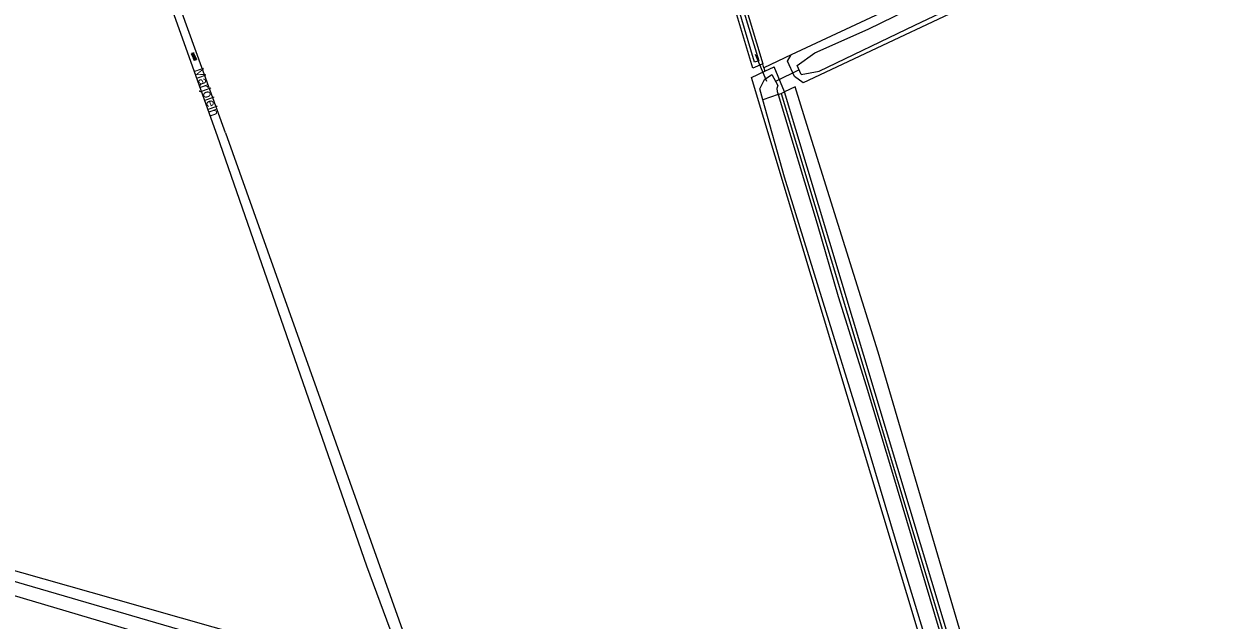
# Model space of a CAD drawing. Extents: x 134297 to 137000, y 403500 to 406000.
# Drawn here: x 135669.7 to 135992.6, y 404160 to 404321.6 of the extents above; entities that cross this region are included whole.
import ezdxf

# ---------------------------------------------------------------- set-up
doc = ezdxf.new("R2010")
doc.units = 0
for name, color, linetype in [('gg-anno-openbare ruimte label', 7, 'Continuous'), ('gg-knt-bronhoudergrens', 7, 'Continuous'), ('gg-knt-onverhard', 7, 'Continuous'), ('gg-kntw-bovenkant insteek waterloop', 7, 'Continuous'), ('gg-kntw-waterlijn', 7, 'Continuous'), ('gg-kwrk-duiker nz buis', 7, 'Continuous'), ('gt-grn-vlakafsluiter', 7, 'Continuous'), ('gt-symb-overige verharding', 7, 'Continuous')]:
    doc.layers.add(name, color=color, linetype=linetype)

# ---------------------------------------------------------------- blocks, each defined once
blk = doc.blocks.new('gt0-OVH')
at = {"layer": 'gt-symb-overige verharding'}
for points in [[(-0.97, 0.3), (-0.97, 0.31), (-0.96, 0.32), (-0.97, 0.33), (-0.97, 0.34), (-0.98, 0.35), (-0.99, 0.35), (-1, 0.36), (-1.01, 0.35), (-1.02, 0.35), (-1.03, 0.34), (-1.03, 0.33), (-1.04, 0.32), (-1.03, 0.31), (-1.03, 0.3), (-1.02, 0.29), (-1.01, 0.29), (-1, 0.28), (-0.99, 0.29), (-0.98, 0.29)], [(-0.87, 0.11), (-0.87, 0.12), (-0.86, 0.13), (-0.87, 0.14), (-0.87, 0.15), (-0.88, 0.16), (-0.89, 0.16), (-0.9, 0.16), (-0.91, 0.16), (-0.92, 0.16), (-0.93, 0.15), (-0.93, 0.14), (-0.94, 0.13), (-0.93, 0.12), (-0.93, 0.11), (-0.92, 0.1), (-0.91, 0.09), (-0.9, 0.09), (-0.89, 0.09), (-0.88, 0.1)], [(-0.77, 0.3), (-0.77, 0.31), (-0.76, 0.32), (-0.77, 0.33), (-0.77, 0.34), (-0.78, 0.35), (-0.79, 0.35), (-0.8, 0.36), (-0.81, 0.35), (-0.82, 0.35), (-0.83, 0.34), (-0.83, 0.33), (-0.84, 0.32), (-0.83, 0.31), (-0.83, 0.3), (-0.82, 0.29), (-0.81, 0.29), (-0.8, 0.28), (-0.79, 0.29), (-0.78, 0.29)], [(-0.67, 0.11), (-0.67, 0.12), (-0.66, 0.13), (-0.67, 0.14), (-0.67, 0.15), (-0.68, 0.16), (-0.69, 0.16), (-0.7, 0.16), (-0.71, 0.16), (-0.72, 0.16), (-0.73, 0.15), (-0.73, 0.14), (-0.74, 0.13), (-0.73, 0.12), (-0.73, 0.11), (-0.72, 0.1), (-0.71, 0.09), (-0.7, 0.09), (-0.69, 0.09), (-0.68, 0.1)], [(-0.57, 0.3), (-0.57, 0.31), (-0.56, 0.32), (-0.57, 0.33), (-0.57, 0.34), (-0.58, 0.35), (-0.59, 0.35), (-0.6, 0.36), (-0.61, 0.35), (-0.62, 0.35), (-0.63, 0.34), (-0.63, 0.33), (-0.64, 0.32), (-0.63, 0.31), (-0.63, 0.3), (-0.62, 0.29), (-0.61, 0.29), (-0.6, 0.28), (-0.59, 0.29), (-0.58, 0.29)], [(-0.47, 0.11), (-0.47, 0.12), (-0.46, 0.13), (-0.47, 0.14), (-0.47, 0.15), (-0.48, 0.16), (-0.49, 0.16), (-0.5, 0.16), (-0.51, 0.16), (-0.52, 0.16), (-0.53, 0.15), (-0.53, 0.14), (-0.54, 0.13), (-0.53, 0.12), (-0.53, 0.11), (-0.52, 0.1), (-0.51, 0.09), (-0.5, 0.09), (-0.49, 0.09), (-0.48, 0.1)], [(-0.37, 0.3), (-0.37, 0.31), (-0.36, 0.32), (-0.37, 0.33), (-0.37, 0.34), (-0.38, 0.35), (-0.39, 0.35), (-0.4, 0.36), (-0.41, 0.35), (-0.42, 0.35), (-0.43, 0.34), (-0.43, 0.33), (-0.44, 0.32), (-0.43, 0.31), (-0.43, 0.3), (-0.42, 0.29), (-0.41, 0.29), (-0.4, 0.28), (-0.39, 0.29), (-0.38, 0.29)], [(-0.27, 0.11), (-0.27, 0.12), (-0.26, 0.13), (-0.27, 0.14), (-0.27, 0.15), (-0.28, 0.16), (-0.29, 0.16), (-0.3, 0.16), (-0.31, 0.16), (-0.32, 0.16), (-0.33, 0.15), (-0.33, 0.14), (-0.34, 0.13), (-0.33, 0.12), (-0.33, 0.11), (-0.32, 0.1), (-0.31, 0.09), (-0.3, 0.09), (-0.29, 0.09), (-0.28, 0.1)], [(-0.17, 0.3), (-0.17, 0.31), (-0.16, 0.32), (-0.17, 0.33), (-0.17, 0.34), (-0.18, 0.35), (-0.19, 0.35), (-0.2, 0.36), (-0.21, 0.35), (-0.22, 0.35), (-0.23, 0.34), (-0.23, 0.33), (-0.24, 0.32), (-0.23, 0.31), (-0.23, 0.3), (-0.22, 0.29), (-0.21, 0.29), (-0.2, 0.28), (-0.19, 0.29), (-0.18, 0.29)], [(-0.07, 0.11), (-0.07, 0.12), (-0.06, 0.13), (-0.07, 0.14), (-0.07, 0.15), (-0.08, 0.16), (-0.09, 0.16), (-0.1, 0.16), (-0.11, 0.16), (-0.12, 0.16), (-0.13, 0.15), (-0.13, 0.14), (-0.14, 0.13), (-0.13, 0.12), (-0.13, 0.11), (-0.12, 0.1), (-0.11, 0.09), (-0.1, 0.09), (-0.09, 0.09), (-0.08, 0.1)], [(0.03, 0.3), (0.03, 0.31), (0.04, 0.32), (0.03, 0.33), (0.03, 0.34), (0.02, 0.35), (0.01, 0.35), (0, 0.36), (-0.01, 0.35), (-0.02, 0.35), (-0.03, 0.34), (-0.03, 0.33), (-0.04, 0.32), (-0.03, 0.31), (-0.03, 0.3), (-0.02, 0.29), (-0.01, 0.29), (0, 0.28), (0.01, 0.29), (0.02, 0.29)], [(0.13, 0.11), (0.13, 0.12), (0.14, 0.13), (0.13, 0.14), (0.13, 0.15), (0.12, 0.16), (0.11, 0.16), (0.1, 0.16), (0.09, 0.16), (0.08, 0.16), (0.07, 0.15), (0.07, 0.14), (0.06, 0.13), (0.07, 0.12), (0.07, 0.11), (0.08, 0.1), (0.09, 0.09), (0.1, 0.09), (0.11, 0.09), (0.12, 0.1)], [(0.23, 0.3), (0.23, 0.31), (0.24, 0.32), (0.23, 0.33), (0.23, 0.34), (0.22, 0.35), (0.21, 0.35), (0.2, 0.36), (0.19, 0.35), (0.18, 0.35), (0.17, 0.34), (0.17, 0.33), (0.16, 0.32), (0.17, 0.31), (0.17, 0.3), (0.18, 0.29), (0.19, 0.29), (0.2, 0.28), (0.21, 0.29), (0.22, 0.29)], [(0.33, 0.11), (0.33, 0.12), (0.34, 0.13), (0.33, 0.14), (0.33, 0.15), (0.32, 0.16), (0.31, 0.16), (0.3, 0.16), (0.29, 0.16), (0.28, 0.16), (0.27, 0.15), (0.27, 0.14), (0.26, 0.13), (0.27, 0.12), (0.27, 0.11), (0.28, 0.1), (0.29, 0.09), (0.3, 0.09), (0.31, 0.09), (0.32, 0.1)], [(0.43, 0.3), (0.43, 0.31), (0.44, 0.32), (0.43, 0.33), (0.43, 0.34), (0.42, 0.35), (0.41, 0.35), (0.4, 0.36), (0.39, 0.35), (0.38, 0.35), (0.37, 0.34), (0.37, 0.33), (0.36, 0.32), (0.37, 0.31), (0.37, 0.3), (0.38, 0.29), (0.39, 0.29), (0.4, 0.28), (0.41, 0.29), (0.42, 0.29)], [(0.53, 0.11), (0.53, 0.12), (0.54, 0.13), (0.53, 0.14), (0.53, 0.15), (0.52, 0.16), (0.51, 0.16), (0.5, 0.16), (0.49, 0.16), (0.48, 0.16), (0.47, 0.15), (0.47, 0.14), (0.46, 0.13), (0.47, 0.12), (0.47, 0.11), (0.48, 0.1), (0.49, 0.09), (0.5, 0.09), (0.51, 0.09), (0.52, 0.1)], [(0.63, 0.3), (0.63, 0.31), (0.64, 0.32), (0.63, 0.33), (0.63, 0.34), (0.62, 0.35), (0.61, 0.35), (0.6, 0.36), (0.59, 0.35), (0.58, 0.35), (0.57, 0.34), (0.57, 0.33), (0.56, 0.32), (0.57, 0.31), (0.57, 0.3), (0.58, 0.29), (0.59, 0.29), (0.6, 0.28), (0.61, 0.29), (0.62, 0.29)], [(0.73, 0.11), (0.73, 0.12), (0.74, 0.13), (0.73, 0.14), (0.73, 0.15), (0.72, 0.16), (0.71, 0.16), (0.7, 0.16), (0.69, 0.16), (0.68, 0.16), (0.67, 0.15), (0.67, 0.14), (0.66, 0.13), (0.67, 0.12), (0.67, 0.11), (0.68, 0.1), (0.69, 0.09), (0.7, 0.09), (0.71, 0.09), (0.72, 0.1)], [(0.83, 0.3), (0.83, 0.31), (0.84, 0.32), (0.83, 0.33), (0.83, 0.34), (0.82, 0.35), (0.81, 0.35), (0.8, 0.36), (0.79, 0.35), (0.78, 0.35), (0.77, 0.34), (0.77, 0.33), (0.76, 0.32), (0.77, 0.31), (0.77, 0.3), (0.78, 0.29), (0.79, 0.29), (0.8, 0.28), (0.81, 0.29), (0.82, 0.29)], [(0.93, 0.11), (0.93, 0.12), (0.94, 0.13), (0.93, 0.14), (0.93, 0.15), (0.92, 0.16), (0.91, 0.16), (0.9, 0.16), (0.89, 0.16), (0.88, 0.16), (0.87, 0.15), (0.87, 0.14), (0.86, 0.13), (0.87, 0.12), (0.87, 0.11), (0.88, 0.1), (0.89, 0.09), (0.9, 0.09), (0.91, 0.09), (0.92, 0.1)], [(1.03, 0.3), (1.03, 0.31), (1.04, 0.32), (1.03, 0.33), (1.03, 0.34), (1.02, 0.35), (1.01, 0.35), (1, 0.36), (0.99, 0.35), (0.98, 0.35), (0.97, 0.34), (0.97, 0.33), (0.96, 0.32), (0.97, 0.31), (0.97, 0.3), (0.98, 0.29), (0.99, 0.29), (1, 0.28), (1.01, 0.29), (1.02, 0.29)], [(-0.97, -0.14), (-0.97, -0.13), (-0.96, -0.12), (-0.97, -0.11), (-0.97, -0.1), (-0.98, -0.09), (-0.99, -0.09), (-1, -0.08), (-1.01, -0.09), (-1.02, -0.09), (-1.03, -0.1), (-1.03, -0.11), (-1.04, -0.12), (-1.03, -0.13), (-1.03, -0.14), (-1.02, -0.15), (-1.01, -0.15), (-1, -0.16), (-0.99, -0.15), (-0.98, -0.15)], [(-0.87, -0.33), (-0.87, -0.32), (-0.86, -0.31), (-0.87, -0.3), (-0.87, -0.29), (-0.88, -0.28), (-0.89, -0.28), (-0.9, -0.28), (-0.91, -0.28), (-0.92, -0.28), (-0.93, -0.29), (-0.93, -0.3), (-0.94, -0.31), (-0.93, -0.32), (-0.93, -0.33), (-0.92, -0.34), (-0.91, -0.35), (-0.9, -0.35), (-0.89, -0.35), (-0.88, -0.34)], [(-0.77, -0.14), (-0.77, -0.13), (-0.76, -0.12), (-0.77, -0.11), (-0.77, -0.1), (-0.78, -0.09), (-0.79, -0.09), (-0.8, -0.08), (-0.81, -0.09), (-0.82, -0.09), (-0.83, -0.1), (-0.83, -0.11), (-0.84, -0.12), (-0.83, -0.13), (-0.83, -0.14), (-0.82, -0.15), (-0.81, -0.15), (-0.8, -0.16), (-0.79, -0.15), (-0.78, -0.15)], [(-0.67, -0.33), (-0.67, -0.32), (-0.66, -0.31), (-0.67, -0.3), (-0.67, -0.29), (-0.68, -0.28), (-0.69, -0.28), (-0.7, -0.28), (-0.71, -0.28), (-0.72, -0.28), (-0.73, -0.29), (-0.73, -0.3), (-0.74, -0.31), (-0.73, -0.32), (-0.73, -0.33), (-0.72, -0.34), (-0.71, -0.35), (-0.7, -0.35), (-0.69, -0.35), (-0.68, -0.34)], [(-0.57, -0.14), (-0.57, -0.13), (-0.56, -0.12), (-0.57, -0.11), (-0.57, -0.1), (-0.58, -0.09), (-0.59, -0.09), (-0.6, -0.08), (-0.61, -0.09), (-0.62, -0.09), (-0.63, -0.1), (-0.63, -0.11), (-0.64, -0.12), (-0.63, -0.13), (-0.63, -0.14), (-0.62, -0.15), (-0.61, -0.15), (-0.6, -0.16), (-0.59, -0.15), (-0.58, -0.15)], [(-0.47, -0.33), (-0.47, -0.32), (-0.46, -0.31), (-0.47, -0.3), (-0.47, -0.29), (-0.48, -0.28), (-0.49, -0.28), (-0.5, -0.28), (-0.51, -0.28), (-0.52, -0.28), (-0.53, -0.29), (-0.53, -0.3), (-0.54, -0.31), (-0.53, -0.32), (-0.53, -0.33), (-0.52, -0.34), (-0.51, -0.35), (-0.5, -0.35), (-0.49, -0.35), (-0.48, -0.34)], [(-0.37, -0.14), (-0.37, -0.13), (-0.36, -0.12), (-0.37, -0.11), (-0.37, -0.1), (-0.38, -0.09), (-0.39, -0.09), (-0.4, -0.08), (-0.41, -0.09), (-0.42, -0.09), (-0.43, -0.1), (-0.43, -0.11), (-0.44, -0.12), (-0.43, -0.13), (-0.43, -0.14), (-0.42, -0.15), (-0.41, -0.15), (-0.4, -0.16), (-0.39, -0.15), (-0.38, -0.15)], [(-0.27, -0.33), (-0.27, -0.32), (-0.26, -0.31), (-0.27, -0.3), (-0.27, -0.29), (-0.28, -0.28), (-0.29, -0.28), (-0.3, -0.28), (-0.31, -0.28), (-0.32, -0.28), (-0.33, -0.29), (-0.33, -0.3), (-0.34, -0.31), (-0.33, -0.32), (-0.33, -0.33), (-0.32, -0.34), (-0.31, -0.35), (-0.3, -0.35), (-0.29, -0.35), (-0.28, -0.34)], [(-0.17, -0.14), (-0.17, -0.13), (-0.16, -0.12), (-0.17, -0.11), (-0.17, -0.1), (-0.18, -0.09), (-0.19, -0.09), (-0.2, -0.08), (-0.21, -0.09), (-0.22, -0.09), (-0.23, -0.1), (-0.23, -0.11), (-0.24, -0.12), (-0.23, -0.13), (-0.23, -0.14), (-0.22, -0.15), (-0.21, -0.15), (-0.2, -0.16), (-0.19, -0.15), (-0.18, -0.15)], [(-0.07, -0.33), (-0.07, -0.32), (-0.06, -0.31), (-0.07, -0.3), (-0.07, -0.29), (-0.08, -0.28), (-0.09, -0.28), (-0.1, -0.28), (-0.11, -0.28), (-0.12, -0.28), (-0.13, -0.29), (-0.13, -0.3), (-0.14, -0.31), (-0.13, -0.32), (-0.13, -0.33), (-0.12, -0.34), (-0.11, -0.35), (-0.1, -0.35), (-0.09, -0.35), (-0.08, -0.34)], [(0.03, -0.14), (0.03, -0.13), (0.04, -0.12), (0.03, -0.11), (0.03, -0.1), (0.02, -0.09), (0.01, -0.09), (0, -0.08), (-0.01, -0.09), (-0.02, -0.09), (-0.03, -0.1), (-0.03, -0.11), (-0.04, -0.12), (-0.03, -0.13), (-0.03, -0.14), (-0.02, -0.15), (-0.01, -0.15), (0, -0.16), (0.01, -0.15), (0.02, -0.15)], [(0.13, -0.33), (0.13, -0.32), (0.14, -0.31), (0.13, -0.3), (0.13, -0.29), (0.12, -0.28), (0.11, -0.28), (0.1, -0.28), (0.09, -0.28), (0.08, -0.28), (0.07, -0.29), (0.07, -0.3), (0.06, -0.31), (0.07, -0.32), (0.07, -0.33), (0.08, -0.34), (0.09, -0.35), (0.1, -0.35), (0.11, -0.35), (0.12, -0.34)], [(0.23, -0.14), (0.23, -0.13), (0.24, -0.12), (0.23, -0.11), (0.23, -0.1), (0.22, -0.09), (0.21, -0.09), (0.2, -0.08), (0.19, -0.09), (0.18, -0.09), (0.17, -0.1), (0.17, -0.11), (0.16, -0.12), (0.17, -0.13), (0.17, -0.14), (0.18, -0.15), (0.19, -0.15), (0.2, -0.16), (0.21, -0.15), (0.22, -0.15)], [(0.33, -0.33), (0.33, -0.32), (0.34, -0.31), (0.33, -0.3), (0.33, -0.29), (0.32, -0.28), (0.31, -0.28), (0.3, -0.28), (0.29, -0.28), (0.28, -0.28), (0.27, -0.29), (0.27, -0.3), (0.26, -0.31), (0.27, -0.32), (0.27, -0.33), (0.28, -0.34), (0.29, -0.35), (0.3, -0.35), (0.31, -0.35), (0.32, -0.34)], [(0.43, -0.14), (0.43, -0.13), (0.44, -0.12), (0.43, -0.11), (0.43, -0.1), (0.42, -0.09), (0.41, -0.09), (0.4, -0.08), (0.39, -0.09), (0.38, -0.09), (0.37, -0.1), (0.37, -0.11), (0.36, -0.12), (0.37, -0.13), (0.37, -0.14), (0.38, -0.15), (0.39, -0.15), (0.4, -0.16), (0.41, -0.15), (0.42, -0.15)], [(0.53, -0.33), (0.53, -0.32), (0.54, -0.31), (0.53, -0.3), (0.53, -0.29), (0.52, -0.28), (0.51, -0.28), (0.5, -0.28), (0.49, -0.28), (0.48, -0.28), (0.47, -0.29), (0.47, -0.3), (0.46, -0.31), (0.47, -0.32), (0.47, -0.33), (0.48, -0.34), (0.49, -0.35), (0.5, -0.35), (0.51, -0.35), (0.52, -0.34)], [(0.63, -0.14), (0.63, -0.13), (0.64, -0.12), (0.63, -0.11), (0.63, -0.1), (0.62, -0.09), (0.61, -0.09), (0.6, -0.08), (0.59, -0.09), (0.58, -0.09), (0.57, -0.1), (0.57, -0.11), (0.56, -0.12), (0.57, -0.13), (0.57, -0.14), (0.58, -0.15), (0.59, -0.15), (0.6, -0.16), (0.61, -0.15), (0.62, -0.15)], [(0.73, -0.33), (0.73, -0.32), (0.74, -0.31), (0.73, -0.3), (0.73, -0.29), (0.72, -0.28), (0.71, -0.28), (0.7, -0.28), (0.69, -0.28), (0.68, -0.28), (0.67, -0.29), (0.67, -0.3), (0.66, -0.31), (0.67, -0.32), (0.67, -0.33), (0.68, -0.34), (0.69, -0.35), (0.7, -0.35), (0.71, -0.35), (0.72, -0.34)], [(0.83, -0.14), (0.83, -0.13), (0.84, -0.12), (0.83, -0.11), (0.83, -0.1), (0.82, -0.09), (0.81, -0.09), (0.8, -0.08), (0.79, -0.09), (0.78, -0.09), (0.77, -0.1), (0.77, -0.11), (0.76, -0.12), (0.77, -0.13), (0.77, -0.14), (0.78, -0.15), (0.79, -0.15), (0.8, -0.16), (0.81, -0.15), (0.82, -0.15)], [(0.93, -0.33), (0.93, -0.32), (0.94, -0.31), (0.93, -0.3), (0.93, -0.29), (0.92, -0.28), (0.91, -0.28), (0.9, -0.28), (0.89, -0.28), (0.88, -0.28), (0.87, -0.29), (0.87, -0.3), (0.86, -0.31), (0.87, -0.32), (0.87, -0.33), (0.88, -0.34), (0.89, -0.35), (0.9, -0.35), (0.91, -0.35), (0.92, -0.34)], [(1.03, -0.14), (1.03, -0.13), (1.04, -0.12), (1.03, -0.11), (1.03, -0.1), (1.02, -0.09), (1.01, -0.09), (1, -0.08), (0.99, -0.09), (0.98, -0.09), (0.97, -0.1), (0.97, -0.11), (0.96, -0.12), (0.97, -0.13), (0.97, -0.14), (0.98, -0.15), (0.99, -0.15), (1, -0.16), (1.01, -0.15), (1.02, -0.15)]]:
    blk.add_lwpolyline(points, close=True, dxfattribs=at)

msp = doc.modelspace()

# ---------------------------------------------------------------- linework, layer by layer
at = {"layer": 'gg-knt-bronhoudergrens'}
for q in [(135870.01, 404310.73), (135870.6, 404308.73)]:
    msp.add_line((135870.31, 404309.69), q, dxfattribs=at)
msp.add_lwpolyline([(135716.77, 404151.88), (135628.13, 404178.22), (135538.9, 404204.96)], dxfattribs=at)
at = {"layer": 'gg-knt-onverhard'}
for p, q in [((135722.25, 404291.15), (135710.12, 404325.06)), ((135724.39, 404292.09), (135712.31, 404325.45)), ((135878.77, 404304.55), (135875.88, 404303.19))]:
    msp.add_line(p, q, dxfattribs=at)
for points in [[(135934.3, 404109.26), (135915.84, 404170.54), (135875.88, 404303.19)], [(135937.23, 404110.38), (135901.24, 404232.63), (135881.51, 404295.78), (135878.77, 404304.55)], [(135774.43, 404143.01), (135762.73, 404174.66), (135722.25, 404291.15)], [(135724.39, 404292.09), (135782.7, 404128.13), (135775.36, 404125.52), (135773.51, 404121.05), (135776.43, 404110.7), (135799.25, 404057.97), (135802, 404054.68)], [(135774.43, 404143.01), (135694.68, 404165.6), (135541.03, 404209.12), (135541.25, 404205.62), (135632.54, 404180.6), (135775.98, 404138.82)]]:
    msp.add_lwpolyline(points, dxfattribs=at)
at = {"layer": 'gg-kntw-bovenkant insteek waterloop'}
for p, q in [((135856.14, 404357.26), (135870.01, 404310.73)), ((135870.6, 404308.73), (135873.09, 404309.91)), ((135875.88, 404303.19), (135873.09, 404309.91)), ((135874.96, 404302.76), (135875.88, 404303.19)), ((135874.96, 404302.76), (135931.72, 404114.35))]:
    msp.add_line(p, q, dxfattribs=at)
for points in [[(136232.4, 404483.42), (136229.09, 404483.22), (136211.35, 404474.91), (136179.65, 404459.33), (136143.55, 404441.91), (136089.18, 404415.38), (136050.09, 404396.55), (136020.57, 404382.16), (135988.75, 404366.64), (135931.54, 404338.35), (135877.73, 404313.16)], [(136000, 404361.71), (135880.94, 404305.58), (135878.61, 404307.31), (135876.7, 404311.45), (135877.73, 404313.16)], [(135870.01, 404310.73), (135867.31, 404309.61), (135852.72, 404358.41)], [(135925.25, 404113.42), (135866.93, 404307.01), (135870.6, 404308.73)]]:
    msp.add_lwpolyline(points, dxfattribs=at)
at = {"layer": 'gg-kntw-waterlijn'}
msp.add_line((135880.4, 404307.88), (135885.33, 404308.76), dxfattribs=at)
for points in [[(135884.16, 404313.75), (135898.53, 404320.11), (135926.42, 404333.8), (135951.05, 404345.14), (135965.34, 404352.44), (136021.67, 404379.51), (136084.87, 404410.41), (136126.48, 404430.96), (136169.18, 404451.47), (136204.36, 404468.59), (136233.6, 404482.32), (136235.31, 404482.99), (136237.37, 404483.02), (136237.66, 404482.34)], [(135885.33, 404308.76), (135911.22, 404321.24), (135977.2, 404352.57), (135993.05, 404360.74), (136022.28, 404374.43), (136052.47, 404388.81), (136081.4, 404402.63), (136112.63, 404418.58), (136144.64, 404434.05), (136190.99, 404456.03), (136224.47, 404472.11), (136236.59, 404477.67), (136237.28, 404476.11)], [(135867.78, 404311.24), (135854.48, 404356.01), (135852.34, 404365.16), (135850.49, 404378.87), (135851.08, 404378.95), (135851.86, 404377.38), (135852.68, 404376.98), (135853.09, 404376.23), (135852.4, 404374.19), (135853.16, 404365.1), (135855.75, 404354.71), (135868.92, 404311.61), (135867.78, 404311.24)], [(135880.4, 404307.88), (135879.3, 404310.27), (135884.16, 404313.75)], [(135870.05, 404301.02), (135869.21, 404303.99), (135870.43, 404306.51), (135872.47, 404307.88), (135874.11, 404304.93), (135873.79, 404304.03), (135873.91, 404303.25), (135874.14, 404302.47)], [(135925.34, 404113.11), (135925.5, 404113.18), (135925.86, 404114.08), (135925.5, 404116.89), (135920.45, 404134.36), (135907.52, 404176.72), (135897.57, 404210.1), (135885.16, 404249.98), (135875.9, 404280.09), (135870.05, 404301.02)], [(135874.14, 404302.47), (135884.77, 404267.45), (135890.41, 404247.77), (135898.01, 404223.48), (135905.14, 404199.84), (135921.64, 404144.65), (135930.69, 404113.93)]]:
    msp.add_lwpolyline(points, dxfattribs=at)
at = {"layer": 'gg-kwrk-duiker nz buis'}
for p, q in [((135867.93, 404313.37), (135870.99, 404306.02)), ((135873.7, 404306.16), (135879.79, 404309.17))]:
    msp.add_line(p, q, dxfattribs=at)
at = {"layer": 'gt-grn-vlakafsluiter'}
for p, q in [((135877.73, 404313.16), (135870.31, 404309.69)), ((135874.14, 404302.47), (135870.05, 404301.02)), ((135874.14, 404302.47), (135874.96, 404302.76))]:
    msp.add_line(p, q, dxfattribs=at)

# ---------------------------------------------------------------- block references
at = {"layer": 'gt-symb-overige verharding', "rotation": -67.10240897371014}
msp.add_blockref('gt0-OVH', (135715.8, 404312.74), dxfattribs=at)

# ---------------------------------------------------------------- texts
at = {"layer": 'gg-anno-openbare ruimte label'}
msp.add_text('Marjolein', height=2.5, rotation=289.6, dxfattribs=at).set_placement((135715.94, 404309.12))

doc.saveas('drawing.dxf')
